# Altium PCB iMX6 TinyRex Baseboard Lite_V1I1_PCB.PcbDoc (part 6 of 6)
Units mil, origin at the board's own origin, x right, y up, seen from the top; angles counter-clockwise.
Board outline 3149.61 x 3543.31 mil, 6 copper layers (L1, L2, L3, L4 (PWR), L5, L6), stack 60.634 mil thick; 385 components, 309 nets, 1566 pads, 914 vias.
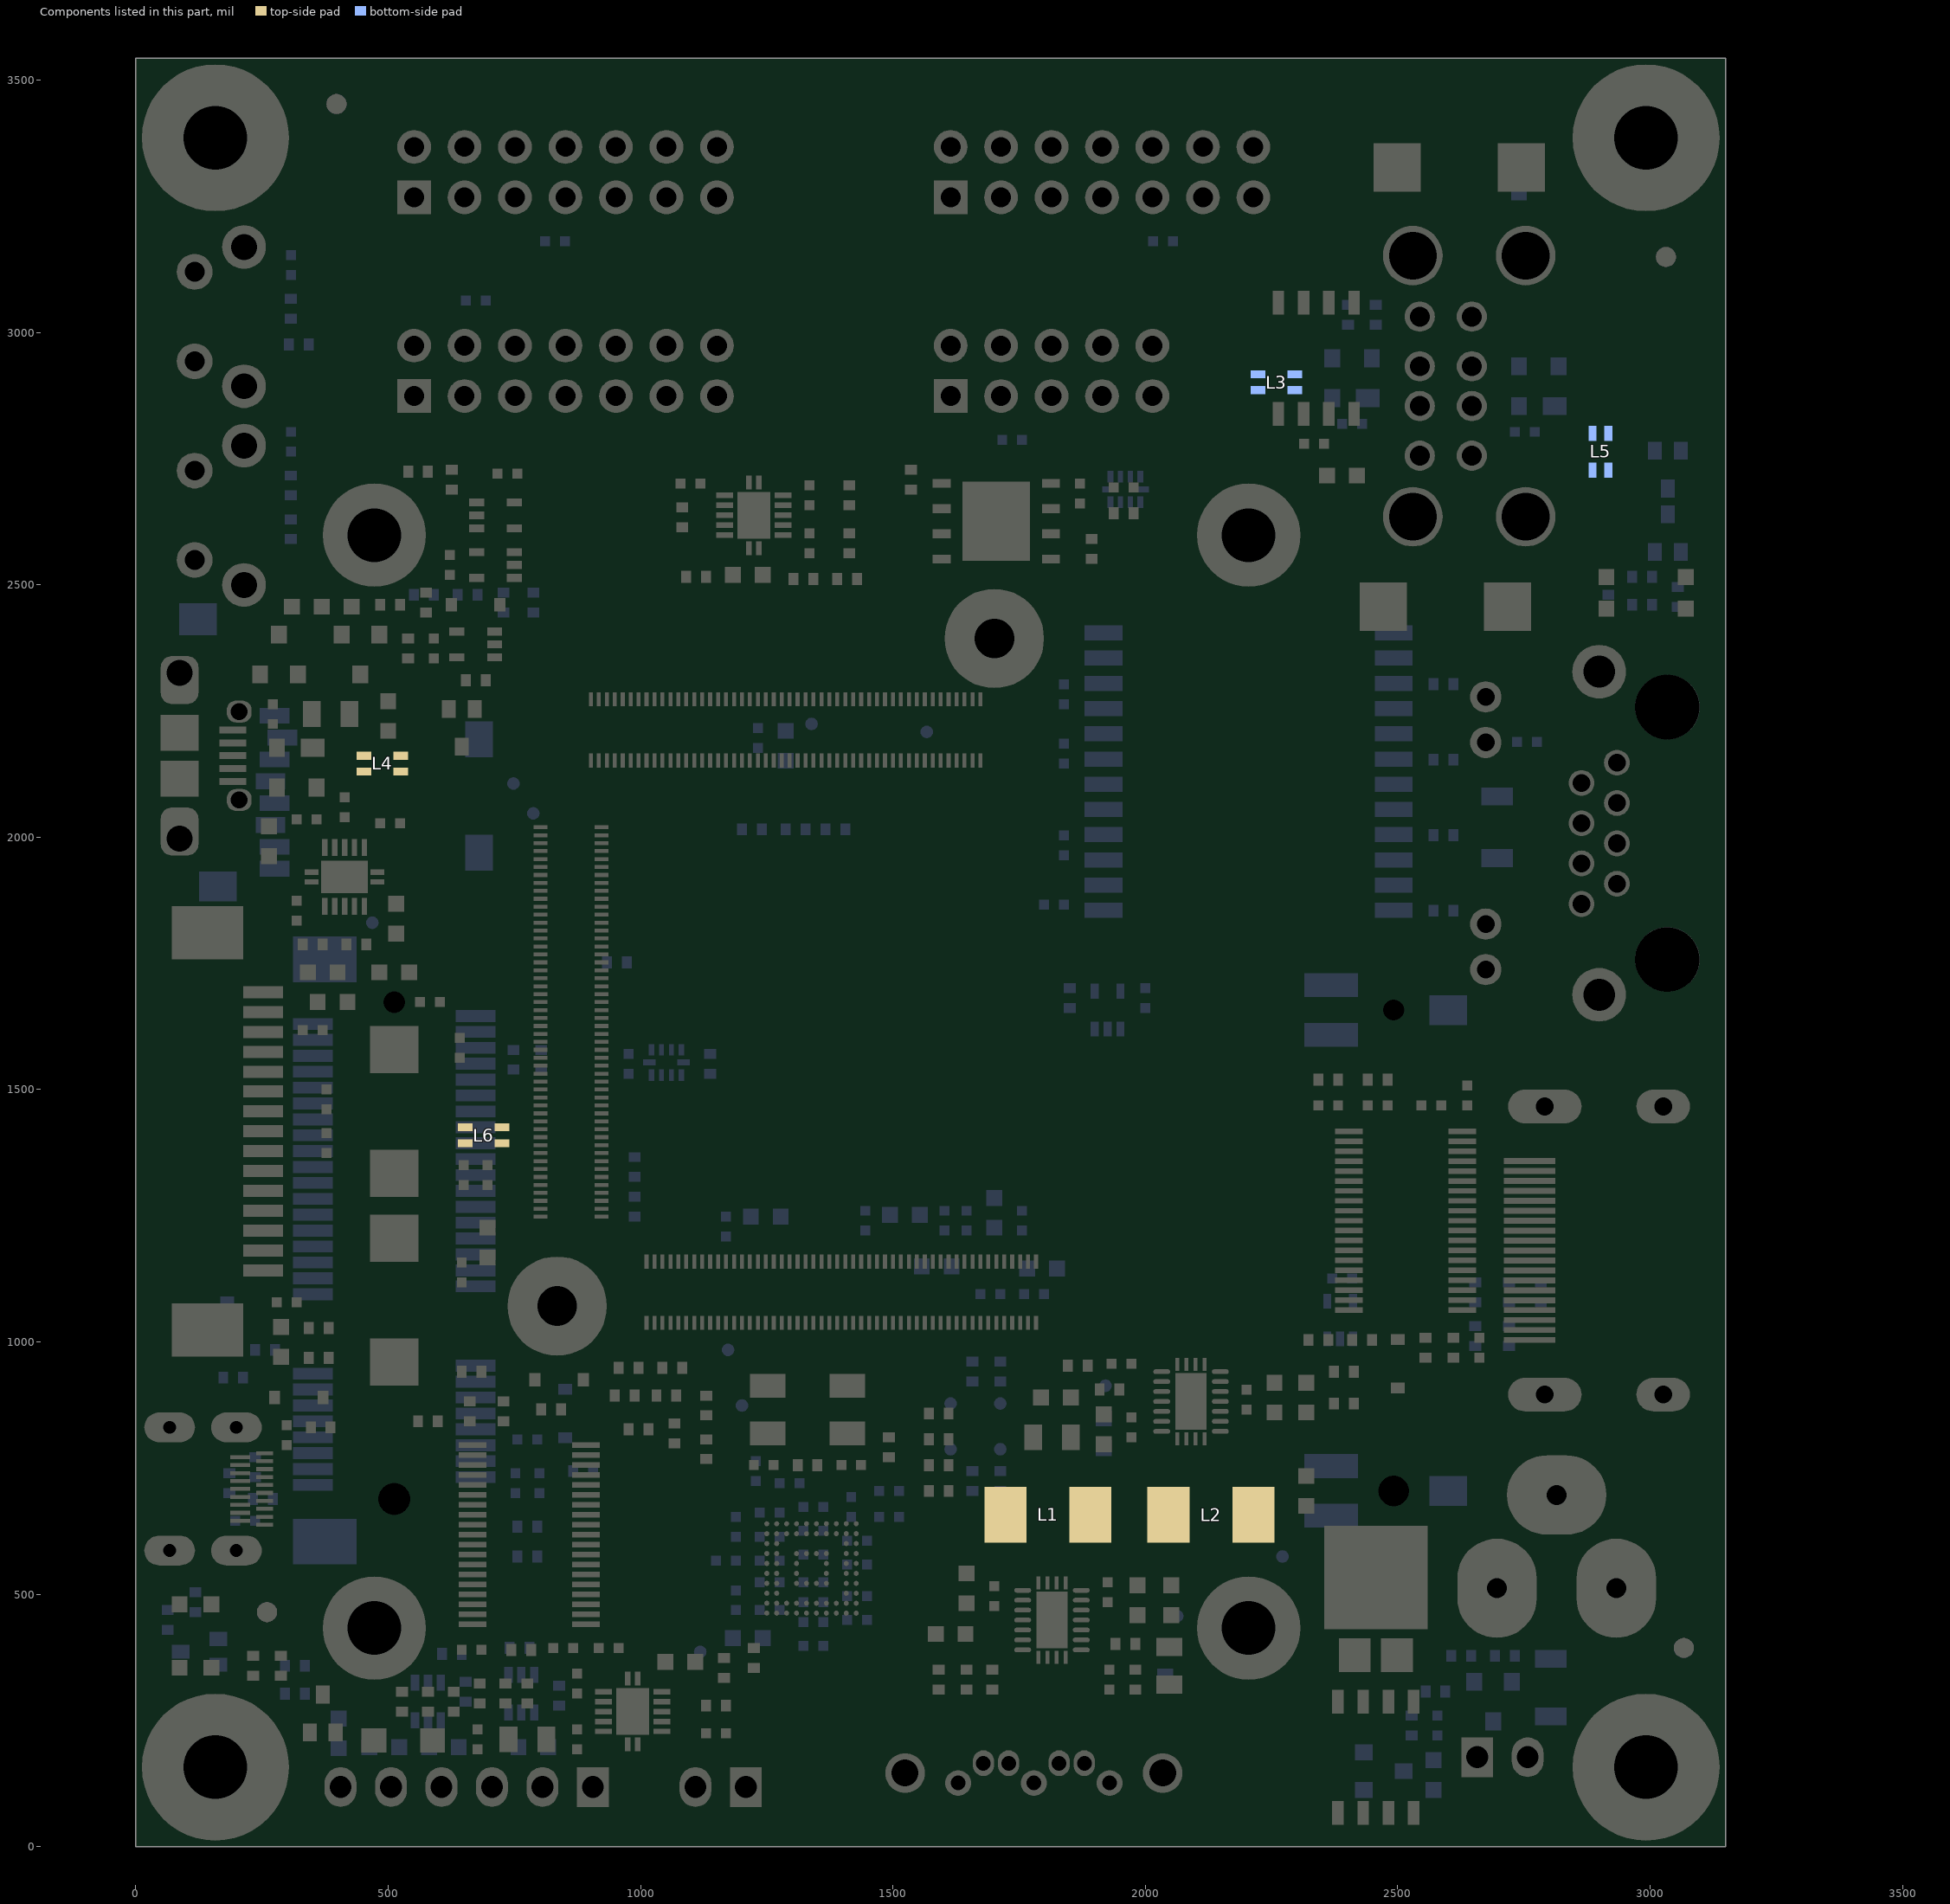
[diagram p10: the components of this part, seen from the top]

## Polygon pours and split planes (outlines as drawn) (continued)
L2_5V on L1 "Power Plane" (solid, pour order 154): 1866.14,484.25 1885.83,484.25 1901.57,500 1905.51,503.94 1905.51,527.56 1905.51,566.93 1917.32,578.74 1933.07,594.49 1933.07,606.3 1933.07,712.6 1850.39,712.6 1850.39,602.36 1850.39,551.18 1866.14,535.43
L1_5V on L1 "Power Plane" (solid, pour order 155): 1763.78,484.25 1763.78,590.55 1763.78,712.6 1681.1,712.6 1681.1,586.61 1712.6,555.12 1720.47,547.24 1720.47,515.75 1720.47,500 1736.22,484.25
GND on L1 "Power Plane" (solid, pour order 156): 1629.92,527.56 1657.48,527.56 1673.23,511.81 1681.1,511.81 1685.04,515.75 1685.04,562.99 1681.1,566.93 1673.23,566.93 1669.29,566.93 1661.42,559.06 1629.92,559.06 1629.92,527.56
GND on L1 "Power Plane" (solid, pour order 157): 1566.93,437.01 1566.93,385.83 1574.8,377.95 1622.05,377.95 1625.98,381.89 1625.98,385.83 1625.98,389.76 1618.11,397.64 1614.17,397.64 1610.24,397.64 1598.43,409.45 1598.43,437.01
GND on L1 "Power Plane" (solid, pour order 158): 2240.16,901.57 2240.16,952.76 2244.09,956.69 2326.77,956.69 2330.71,956.69 2334.65,952.76 2334.65,901.57 2303.15,901.57 2291.34,913.39 2283.46,913.39 2271.65,901.57 2240.16,901.57
+VIN on L1 "Power Plane" (solid, pour order 159): 2149.61,885.83 2149.61,858.27 2173.23,858.27 2212.6,818.9 2326.77,818.9 2334.65,818.9 2334.65,826.77 2334.65,877.95 2232.28,877.95 2192.91,877.95 2185.04,885.83 2173.23,885.83
L2_3V3 on L1 "Power Plane" (solid, pour order 160): 2039.37,846.46 2039.37,795.28 2082.68,751.97 2086.61,748.03 2086.61,700.79 2086.61,602.36 2003.94,602.36 2003.94,736.22 1992.13,748.03 1992.13,826.77 2011.81,846.46
L1_3V3 on L1 "Power Plane" (solid, pour order 161): 2141.73,846.46 2141.73,771.65 2173.23,740.16 2173.23,708.66 2173.23,602.36 2255.91,602.36 2255.91,732.28 2185.04,803.15 2185.04,826.77 2165.35,846.46
+3V3 on L1 "Power Plane" (solid, pour order 162): 22 vertices, not listed, extent 1834.65,783.46 2031.5,917.32
GND on L1 "Power Plane" (solid, pour order 163): 1901.57,811.02 1933.07,811.02 1944.88,799.21 1944.88,755.91 1944.88,751.97 1940.94,748.03 1893.7,748.03 1889.76,751.97 1889.76,787.4 1897.64,795.28 1901.57,799.21 1901.57,811.02
GND on L1 "Power Plane" (solid, pour order 164): 1751.97,858.27 1751.97,905.51 1755.91,909.45 1803.15,909.45 1807.09,905.51 1807.09,870.08 1791.34,854.33 1759.84,854.33 1755.91,854.33 1751.97,858.27
GND on L1 "Power Plane" (solid, pour order 165): 1795.28,838.58 1795.28,771.65 1783.46,759.84 1744.09,759.84 1740.16,763.78 1736.22,767.72 1736.22,783.46 1736.22,787.4 1744.09,795.28 1759.84,811.02 1759.84,838.58 1795.28,838.58
+2V5 on L1 "Power Plane" (solid, pour order 174): 1169.29,2622.05 1169.29,2562.99 1196.85,2535.43 1196.85,2480.31 1196.85,2468.5 1188.98,2460.63 1149.61,2460.63 1122.05,2488.19 1122.05,2535.43 1110.24,2547.24 1110.24,2574.8 1110.24,2590.55 1141.73,2622.05
GND on L1 "Power plane" (solid, pour order 167): 968.5,187.2 1000,187.2 1000,218.7 1015.75,218.7 1015.75,317.13 1000,317.13 1000,348.62 968.5,348.62 968.5,317.13 952.76,317.13 952.76,218.7 968.5,218.7 968.5,187.2
GND on L1 "Power plane" (solid, pour order 168): 332.87,1937.01 332.87,1905.51 364.37,1905.51 364.37,1889.76 462.8,1889.76 462.8,1905.51 494.29,1905.51 494.29,1937.01 462.8,1937.01 462.8,1952.76 364.37,1952.76 364.37,1937.01 332.87,1937.01
GND on L1 "Power plane" (solid, pour order 169): 1240.16,2718.31 1208.66,2718.31 1208.66,2686.81 1192.91,2686.81 1192.91,2588.39 1208.66,2588.39 1208.66,2556.89 1240.16,2556.89 1240.16,2588.39 1255.91,2588.39 1255.91,2686.81 1240.16,2686.81 1240.16,2718.31
+V_INPUT on L1 "Power Plane" (solid, pour order 107): 17 vertices, not listed, extent 2185.04,39.37 2775.59,602.36
+VIN_D on L1 "Power Plane" (solid, pour order 109): 2543.31,263.78 2586.61,307.09 2586.61,413.39 2350.39,413.39 2279.53,342.52 2279.53,263.78
+VIN on L1 "Power Plane" (solid, pour order 111): 22 vertices, not listed, extent 2208.66,433.07 2586.61,877.95
+V_INPUT on L6 "Power Plane" (solid, pour order 123): 27 vertices, not listed, extent 2185.04,78.74 2834.65,586.61
+5V on L6 "Power Plane" (solid, pour order 122): 2724.41,3291.34 2755.91,3291.34 2767.72,3279.53 2767.72,3248.03 2767.72,3240.16 2763.78,3236.22 2716.54,3236.22 2712.6,3240.16 2712.6,3267.72 2712.6,3279.53 2724.41,3291.34
+V_INPUT on L6 "Power Plane" (solid, pour order 121): 2688.98,216.54 2688.98,137.8 2602.36,137.79 2586.61,153.54 2555.12,153.54 2555.12,188.98 2566.93,200.79 2566.93,228.35 2594.49,228.35 2606.3,216.54
+5V_HDMI_IN_CON on L6 "Power Plane" (solid, pour order 114): 20 vertices, not listed, extent 165.35,913.39 275.59,996.06
+3V3 on L6 "Power Plane" (solid, pour order 110): 34 vertices, not listed, extent 2645.67,2157.48 3086.61,2464.57
GND on L6 "Power Plane" (solid, pour order 143): 82.68,1901.57 141.73,1960.63 204.72,1960.63 212.6,1952.76 212.6,1870.08 157.48,1814.96 157.48,1748.03 157.48,1736.22 149.61,1728.35 118.11,1728.35 94.49,1728.35 82.68,1740.16
+VIN on L6 "Power Plane" (solid, pour order 199): 22 vertices, not listed, extent 1181.1,2559.05 1555.12,3425.2
+1V5_MPCIE on L6 "Power Plane" (solid, pour order 195): 44 vertices, not listed, extent 492.13,795.28 787.4,1712.6
+3V3_TVDD on L6 "Power Plane" (solid, pour order 191): 1244.09,622.05 1244.09,555.12 1181.1,555.12 1181.1,622.05 1244.09,622.05
+5V_USB1_VBUS on L6 "Power Plane" (solid, pour order 190): 17 vertices, not listed, extent 2236.22,2984.25 2759.84,3366.14
+5V on L6 "Power Plane" (solid, pour order 186): 1149.61,1216.54 1165.35,1216.54 1177.17,1216.54 1188.98,1228.35 1192.91,1232.28 1192.91,1255.91 1200.79,1263.78 1232.28,1263.78 1232.28,1220.47 1200.79,1188.98 1141.73,1188.98 1137.8,1192.91 1137.8,1204.72
GND on L6 "Power Plane" (solid, pour order 185): 1263.78,1232.28 1263.78,1267.72 1259.84,1271.65 1251.97,1279.53 1251.97,1283.46 1255.91,1287.4 1259.84,1287.4 1275.59,1287.4 1287.4,1275.59 1291.34,1271.65 1291.34,1236.22 1291.34,1232.28 1287.4,1232.28 1263.78,1232.28 1263.78,1263.78
+VIN on L6 "Power Plane" (solid, pour order 184): 30 vertices, not listed, extent 1602.36,1055.12 1783.46,1240.16
+3V3 on L6 "Power Plane" (solid, pour order 183): 27 vertices, not listed, extent 1429.13,1177.17 1625.98,1267.72
GND on L6 "Power Plane" (solid, pour order 182): 1570.87,1133.86 1570.87,1188.98 1566.93,1192.91 1562.99,1196.85 1555.12,1196.85 1515.75,1196.85 1507.87,1188.98 1507.87,1165.35 1539.37,1133.86 1570.87,1133.86
GND on L6 "Power Plane" (solid, pour order 181): 1539.37,1236.22 1570.87,1236.22 1586.61,1251.97 1606.3,1251.97 1614.17,1251.97 1614.17,1283.46 1602.36,1295.28 1547.24,1295.28 1539.37,1287.4
GND on L6 "Power Plane" (solid, pour order 179): 1677.17,1326.77 1724.41,1326.77 1728.35,1322.83 1728.35,1279.53 1720.47,1271.65 1681.1,1271.65 1673.23,1279.53 1673.23,1291.34 1673.23,1322.83 1677.17,1326.77
GND on L6 "Power Plane" (solid, pour order 180): 1866.14,1174.94 1866.14,1122.05 1862.2,1118.11 1818.9,1118.11 1811.02,1125.98 1811.02,1173.23 1826.77,1188.98 1852.11,1188.98
GND on L6 "Power Plane" (solid, pour order 178): 1417.32,503.94 1417.32,440.94 1397.64,440.94 1381.89,456.69 1381.89,500 1389.76,507.87 1417.32,507.87 1417.32,503.94
GND on L6 "Power Plane" (solid, pour order 177): 27 vertices, not listed, extent 1228.35,397.64 1358.27,673.23
+2V5 on L6 "Power Plane" (solid, pour order 176): 1220.47,2208.66 1248.03,2208.66 1259.84,2196.85 1287.4,2196.85 1326.77,2196.85 1350.39,2220.47 1350.39,2232.28 1334.65,2248.03 1228.35,2248.03 1224.41,2244.09 1220.47,2240.16
+3V3_MPCIE on L6 "Power Plane" (solid, pour order 175): 740.16,732.28 807.09,732.28 807.09,751.97 771.65,787.4 759.84,787.4 755.91,787.4 748.03,779.53 740.16,771.65 740.16,732.28
+5V_USB1_VBUS on L6 "Power Plane" (solid, pour order 131): 21 vertices, not listed, extent 2622.05,2728.35 2834.65,2870.08
+5V_USB0_VBUS on L6 "Power Plane" (solid, pour order 132): 19 vertices, not listed, extent 2397.64,2507.87 2547.24,2889.76
GND on L6 "Power Plane" (solid, pour order 133): 2740.16,1976.38 2740.16,1925.2 2732.28,1917.32 2677.17,1917.32 2661.42,1917.32 2653.54,1925.2 2653.54,1976.38
GND on L6 "Power Plane" (solid, pour order 147): 70.87,2488.19 70.87,2413.39 153.54,2330.71 192.91,2330.71 200.79,2330.71 208.66,2338.58 208.66,2413.39 161.42,2460.63 153.54,2468.5 153.54,2480.31 153.54,2488.19 145.67,2496.06 114.17,2496.06 78.74,2496.06
GND on L6 "Power Plane" (solid, pour order 148): 448.82,1696.85 456.69,1704.72 456.69,1795.28 440.94,1811.02 413.39,1838.58 311.02,1838.58 303.15,1838.58 271.65,1807.09 271.65,1740.16 303.15,1708.66 307.09,1708.66 421.26,1708.66 433.07,1696.85 454.72,1696.85
GND on L6 "Power Plane" (solid, pour order 149): 19 vertices, not listed, extent 287.4,492.13 460.63,688.98
+5V on L6 "Power Plane" (solid, pour order 170): 2023.62,381.89 2055.12,381.89 2066.93,393.7 2070.87,397.64 2070.87,433.07 2066.93,437.01 1984.25,437.01 1980.32,437.01 1976.38,433.07 1976.38,425.2 1976.38,421.26 2015.75,381.89 2055.12,381.89
GND on L6 "Power Plane" (solid, pour order 171): 2055.12,350.39 2066.93,350.39 2106.3,311.02 2106.3,291.34 2090.55,275.59 2023.62,275.59 2015.75,283.46 2015.75,342.52 2023.62,350.39 2066.93,350.39
GND on L6 "Power Plane" (solid, pour order 172): 1940.94,803.15 1944.88,799.21 1944.88,751.97 1940.94,748.03 1897.64,748.03 1893.7,748.03 1889.76,751.97 1889.76,791.34 1901.57,803.15
+3V3 on L6 "Power Plane" (solid, pour order 173): 1877.95,893.7 1877.95,814.96 1881.89,811.02 1889.76,811.02 1893.7,814.96 1893.7,818.9 1893.7,822.83 1905.51,834.65 1933.07,834.65 1933.07,921.26 1929.13,925.2 1925.2,925.2 1909.45,925.2 1877.95,893.7 1877.95,885.83
GND on L6 "Power Plane" (solid, pour order 113): 2287.4,732.28 2291.34,728.35 2322.83,728.35 2440.94,728.35 2448.82,736.22 2448.82,791.34 2444.88,791.34 2440.94,795.28 2311.02,795.28 2287.4,771.65 2283.46,767.72 2283.46,740.16 2283.46,736.22 2287.4,732.28
GND on L6 "Power Plane" (solid, pour order 115): 2279.53,696.85 2291.34,708.66 2322.83,708.66 2342.52,688.98 2350.39,681.1 2421.26,681.1 2421.26,629.92 2311.02,629.92 2279.53,661.42
GND on L6 "Power Plane" (solid, pour order 117): 2535.43,732.28 2535.43,677.17 2539.37,673.23 2661.42,673.23 2669.29,681.1 2669.29,732.28 2665.35,736.22 2539.37,736.22
GND on L6 "Power Plane" (solid, pour order 116): 2535.43,1685.04 2535.43,1629.92 2539.37,1625.98 2661.42,1625.98 2669.29,1633.86 2669.29,1685.04 2665.35,1688.98 2539.37,1688.98
GND on L6 "Power Plane" (solid, pour order 119): 2291.34,1590.55 2299.21,1582.68 2440.94,1582.68 2452.76,1594.49 2452.76,1618.11 2437.01,1633.86 2433.07,1633.86 2299.21,1633.86 2291.34,1625.98 2291.34,1590.55
GND on L6 "Power Plane" (solid, pour order 120): 2291.34,1700.79 2314.96,1724.41 2322.83,1732.28 2421.26,1732.28 2433.07,1732.28 2452.76,1712.6 2452.76,1696.85 2452.76,1688.98 2444.88,1681.1 2334.65,1681.1 2314.96,1661.42 2295.28,1661.42 2291.34,1665.35
+3V3 on L3 "Power Plane" (solid, pour order 198): 59.06,236.22 59.06,523.62 244.09,523.62 334.65,433.07 590.55,433.07 712.6,555.12 818.9,555.12 846.46,527.56 846.46,314.96 767.72,236.22
+2V5 on L3 "Power Plane" (solid, pour order 197): 1200.79,2224.41 1240.16,2224.41 1307.09,2224.41 1318.9,2236.22 1318.9,2342.52 1338.58,2362.2 1338.58,2570.87 1318.9,2590.55 1244.09,2590.55 1082.68,2429.13 1082.68,2342.52
+5V on L3 "Power Plane" (solid, pour order 196): 33 vertices, not listed, extent 1968.5,59.06 3090.55,3484.25
+3V3 on L4 (PWR) "Power Plane" (solid, pour order 202): 53 vertices, not listed, extent 59.06,480.31 2677.17,3484.25
+1V8 on L4 (PWR) "Power Plane" (solid, pour order 201): 1106.3,413.39 1181.1,413.39 1220.47,452.76 1279.53,511.81 1437.01,669.29 1496.06,669.29 1496.06,696.85 1464.57,728.35 1161.42,728.35 1161.42,492.13 1141.73,472.44 1082.68,472.44 1082.68,437.01
+VIN on L4 (PWR) "Power Plane" (solid, pour order 200): 62 vertices, not listed, extent 59.05,59.06 3090.55,3484.25
+5V on L4 (PWR) "Power Plane" (solid, pour order 194): 63 vertices, not listed, extent 374.01,267.72 2141.73,2519.69
GND on L2 (split plane): 3145.59,4.01 4.01,4.01 4.01,3539.29 3145.59,3539.29
GND on L5 (split plane): 3145.59,4.01 4.01,4.01 4.01,3539.29 3145.59,3539.29

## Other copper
L6:
  region: 2541.22,3500.79 2541.22,3500.91 2541.22,3501.03 2541.22,3501.16 2541.22,3501.28 2541.22,3501.4 2541.22,3501.52 2541.22,3501.64 2541.22,3501.77 2541.22,3501.89 2541.22,3502.01 2541.22,3502.13 2541.22,3502.25 2541.22,3502.38 2541.22,3502.5 2541.22,3502.62 2541.22,3502.74 2541.22,3502.86 2541.22,3502.99 2541.22,3503.11 2541.22,3503.23 2541.22,3503.35 2541.22,3503.48 2541.22,3503.6 2541.22,3503.72 2541.22,3503.84 2541.22,3503.96 2541.22,3504.09 2541.22,3504.21 2541.22,3504.33 2541.22,3504.45 2541.22,3504.57 2541.22,3504.7 2433.07,3504.7 2433.07,3504.57 2433.07,3504.45 2433.07,3504.33 2433.07,3504.21 2433.07,3504.09 2433.07,3503.96 2433.07,3503.84 2433.07,3503.72 2433.07,3503.6 2433.07,3503.48 2433.07,3503.35 2433.07,3503.23 2433.07,3503.11 2433.07,3502.99 2433.07,3502.86 2433.07,3502.74 2433.07,3502.62 2433.07,3502.5 2433.07,3502.38 2433.07,3502.25 2433.07,3502.13 2433.07,3502.01 2433.07,3501.89 2433.07,3501.77 2433.07,3501.64 2433.07,3501.52 2433.07,3501.4 2433.07,3501.28 2433.07,3501.16 2433.07,3501.03 2433.07,3500.91 2433.07,3500.79 2433.07,3500.67 2541.22,3500.67
  region: 2554.77,3395.2 2554.77,3395.33 2554.77,3395.45 2554.77,3395.57 2554.77,3395.69 2554.77,3395.81 2554.77,3395.94 2554.77,3396.06 2554.77,3396.18 2554.77,3396.3 2554.77,3396.42 2554.77,3396.55 2554.77,3396.67 2554.77,3396.79 2554.77,3396.91 2554.77,3397.03 2554.77,3397.16 2554.77,3397.28 2554.77,3397.4 2554.77,3397.52 2554.77,3397.64 2554.77,3397.77 2554.77,3397.89 2554.77,3398.01 2554.77,3398.13 2554.77,3398.25 2554.77,3398.38 2554.77,3398.5 2554.77,3398.62 2554.77,3398.74 2554.77,3398.87 2554.77,3398.99 2554.77,3399.11 2446.62,3399.11 2446.62,3398.99 2446.62,3398.87 2446.62,3398.74 2446.62,3398.62 2446.62,3398.5 2446.62,3398.38 2446.62,3398.25 2446.62,3398.13 2446.62,3398.01 2446.62,3397.89 2446.62,3397.77 2446.62,3397.64 2446.62,3397.52 2446.62,3397.4 2446.62,3397.28 2446.62,3397.16 2446.62,3397.03 2446.62,3396.91 2446.62,3396.79 2446.62,3396.67 2446.62,3396.55 2446.62,3396.42 2446.62,3396.3 2446.62,3396.18 2446.62,3396.06 2446.62,3395.94 2446.62,3395.81 2446.62,3395.69 2446.62,3395.57 2446.62,3395.45 2446.62,3395.33 2446.62,3395.2 2446.62,3395.08 2554.77,3395.08
  region: 2812 vertices and 0 holes, not listed, extent 2467.25,3412.54 2529.87,3490.17
  region: 1344 vertices and 0 holes, not listed, extent 2677.75,3465.62 2759.66,3504.1
  region: 1381 vertices and 0 holes, not listed, extent 2699.13,3397.75 2762.06,3458.27
  region: 2099 vertices and 0 holes, not listed, extent 2639.01,3396.28 2713.56,3503.97

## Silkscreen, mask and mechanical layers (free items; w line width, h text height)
Top Overlay:
  text "RESET" at 259.84,3122.05 h39.37 r270
  text "USER" at 259.84,2712.6 h39.37 r270
  text "OTG" at 39.37,2480.31 h39.37 r270
  text "USB" at 98.43,2480.31 h39.37 r270
  text "USB TOP" at 2854.33,2381.89 h31.5 r90
  text "USB BOT" at 3011.81,2381.89 h31.5 r90
  text "FEDEVEL" at 2480.31,1803.15 h62.99 r90
  text "(c) 2015" at 2362.2,1787.4 h62.99 r90
  text "& VOIPAC" at 2598.43,1775.59 h62.99 r90
  text "POSITIVE IN" at 2732.28,803.15 h39.37
  text "IN:" at 2519.69,767.72 h39.37 r90
  text "CENTER" at 2909.45,740.16 h39.37
  text "+3.2 to" at 2578.74,649.61 h39.37 r90
  text "5.3V DC" at 2637.8,649.61 h39.37 r90
  text "PWR" at 11.81,523.62 h31.5 r270
  text "USER" at 11.81,405.51 h31.5 r270
  text "G" at 393.7,11.81 h39.37
  text "Y" at 492.13,11.81 h39.37
  text "O" at 594.49,11.81 h39.37
  text "R" at 696.85,11.81 h39.37
  text "Br" at 783.46,11.81 h39.37
  text "Bl" at 885.83,11.81 h39.37
  text "BOOT MODE" at 988.19,11.81 h39.37
Bottom Overlay:
  lines w10: 919.52,2283.49 919.52,2381.92 ; 1037.63,2283.49 1037.63,2381.92 ; 1155.74,2283.49 1155.74,2381.92 ; 1273.85,2283.49 1273.85,2381.92 ; 1391.96,2283.49 1391.96,2381.92 ; 1830.71,323.26 1948.82,323.26 ; 1830.71,441.37 1948.82,441.37 ; 801.41,2283.49 1510.07,2283.49 1510.07,2381.92 801.41,2381.92 801.41,2283.49 ; 1830.71,205.15 1830.71,559.48 1948.82,559.48 1948.82,205.15 1830.71,205.15
  text "PERIPHERALS" at 657.48,3472.44 h39.37 r180
  text "SYSTEM" at 1803.15,3472.44 h39.37 r180
  text "UARTS" at 759.84,3078.74 h39.37 r180
  text "GPIO & PWM" at 1625.98,3078.74 h39.37 r180
  text "USB" at 3110.24,2952.76 h39.37 r90
  text "(c) fedevel.com & voipac.com" at 622.05,2704.72 h46.46 r180
  text "iMX6 TinyRex BB Lite V1I1" at 606.3,2594.49 h62.99 r180
  text "A" at 840.78,2362.23 h60 r180
  text "B" at 958.89,2362.23 h60 r180
  text "C" at 1077,2362.23 h60 r180
  text "D" at 1195.11,2362.23 h60 r180
  text "E" at 1313.22,2362.23 h60 r180
  text "F" at 1431.33,2362.23 h60 r180
  text "MODBOX" at 807.09,2244.09 h51.18 r180
  text "ETHERNET" at 3090.55,2165.35 h39.37 r90
  text "+2V5" at 1374.02,2094.49 h39.37 r270
  text "+1V2" at 1551.18,2019.69 h39.37 r270
  text "FEDEVEL Academy" at 921.26,1944.88 h50 r180
  text "Designed by" at 1031.5,1850.39 h50 r180
  text "+1V5" at 519.69,1834.65 h39.37 r180
  text "HDMI OUT" at 3090.55,1338.58 h39.37 r90
  text "CAMERA IN" at 39.37,1240.16 h39.37 r270
  text "+3V3" at 1901.57,960.63 h39.37 r270
  text "+3V0 ALW" at 1078.74,897.64 h39.37 r270
  text "GND" at 1263.78,818.9 h39.37 r270
  text "INPUT" at 3043.31,787.4 h39.37 r90
  text "POWER" at 3110.24,787.4 h39.37 r90
  text "IN" at 39.37,681.1 h39.37 r270
  text "BOARD" at 2007.87,669.29 h51.18
  text "HDMI" at 106.3,641.73 h39.37 r270
  text "+VIN" at 2212.6,598.43 h39.37 r270
  text "VARIANT:" at 2007.87,590.55 h51.18
  text "to" at 1614.17,511.81 h39.37
  text "+3.2" at 1791.34,511.81 h39.37
  text "+5V" at 2043.31,488.19 h39.37 r270
  text "+5.3V" at 1791.34,452.76 h39.37
  text "+1V8" at 1047.24,425.2 h39.37 r270
  text "+5V" at 1791.34,358.27 h39.37
  text "CUSTOM" at 1791.34,236.22 h39.37
  text "TTL-232R-3V3 FTDI" at 976.38,27.56 h39.37
  text "SATA" at 1866.14,27.56 h39.37
  text "POWER HEADER" at 2846.46,27.56 h39.37
Bottom Solder:
  drawing of 6 lines, arcs and shapes, not listed
Mechanical Drawing All:
  circle w23.62: c511.81,1673.23 r9.84
  circle w35.43: c511.81,688.98 r14.76
  circle w39.37: c2992.13,3385.83 r62.99
  circle w23.62: c834.65,1070.87 r39.37
  circle w39.37: c157.48,3385.83 r62.99
  circle w39.37: c157.48,157.48 r62.99
  circle w39.37: c2992.13,157.48 r62.99
  circle w39.37: c472.44,2598.43 r53.15
  circle w39.37: c472.44,433.07 r53.15
  circle w39.37: c2204.72,2598.43 r53.15
  circle w23.62: c1700.79,2393.7 r39.37
  circle w39.37: c2204.72,433.07 r53.15
  circle w31.5: c2492.13,704.72 r14.76
  circle w31.5: c2492.13,704.72 r14.76
  circle w21.65: c2492.13,1657.48 r9.84
  lines w7.87: -106.3,2161.42 76.77,2161.42 ; -84.49,2112.2 98.58,2112.2 ; 6.1,2637.8 108.46,2637.8 ; 6.1,3031.5 108.46,3031.5 ; 37.4,708.66 220.47,708.66 ; 68.9,1417.32 251.97,1417.32 ; 2969.68,2007.87 3152.76,2007.87 ; 2986.22,2893.7 3153.54,2893.7 ; 2988.19,1181.1 3149.61,1181.1 ; 3068.9,511.81 3149.61,511.81
  lines w39.37: 0,0 0,3543.31 3149.61,3543.31 3149.61,0 0,0
  text "Mechanical Drawing - All" at 0,4429.13 h137.8
  text "iMX6 TinyRex Baseboard Lite" at -492.13,4035.43 h137.8
  text ".VersionRevision" at 3248.03,4035.43 h137.8
  text "(Scale 1:1)" at 1082.68,-1870.08 h60
Manufacturing Notes:
  circle w39.37: c9842.52,5511.81 r9.84
  circle w39.37: c9842.52,3937.01 r9.84
  circle w39.37: c6200.79,3937.01 r9.84
  circle w39.37: c6200.79,5511.81 r9.84
  lines w7.87: 5364.17,4724.41 5413.39,4724.41 ; 5905.51,4724.41 5964.57,4724.41 ; 6102.36,3592.52 9940.94,3592.52 ; 6131.89,3956.69 6181.1,3956.69 6181.1,4005.91 ; 6131.89,5492.13 6181.1,5492.13 6181.1,5442.91 ; 6200.79,3937.01 5413.39,4724.41 ; 6200.79,5511.81 5413.39,4724.41 ; 6259.84,3553.15 6299.21,3592.52 6259.84,3631.89 ; 6299.21,3543.31 6299.21,3838.58 ; 6348.43,5413.39 6348.43,5364.17 ; 6397.64,3543.31 6397.64,3838.58 ; 6397.64,5364.17 6348.43,5364.17 ; 6437.01,3553.15 6397.64,3592.52 6437.01,3631.89 ; 6781.5,3858.27 6830.71,3858.27 6830.71,3907.48 ; 6781.5,5590.55 6830.71,5590.55 6830.71,5541.34 ; 6850.39,3838.58 5964.57,4724.41 ; 6850.39,5610.24 5964.57,4724.41 ; 7677.17,3346.46 8169.29,3346.46 ; 7933.07,3307.09 7972.44,3346.46 7933.07,3385.83 ; 7933.07,3553.15 7972.44,3592.52 7933.07,3631.89 ; 7972.44,3297.24 7972.44,3838.58 ; 7982.28,5551.18 8021.65,5511.81 ; 8021.65,6102.36 8021.65,5511.81 ; 8061.02,5551.18 8021.65,5511.81 ; 8070.87,3297.24 8070.87,3838.58 ; 8110.24,3307.09 8070.87,3346.46 8110.24,3385.83 ; 8110.24,3553.15 8070.87,3592.52 8110.24,3631.89 ; 9192.91,3838.58 10078.74,4724.41 ; 9192.91,5610.24 10078.74,4724.41 ; 9212.6,3907.48 9212.6,3858.27 9261.81,3858.27 ; 9212.6,5541.34 9212.6,5590.55 9261.81,5590.55 ; 9606.3,3553.15 9645.67,3592.52 9606.3,3631.89 ; 9645.67,3543.31 9645.67,3838.58 ; 9645.67,5364.17 9694.88,5364.17 ; 9694.88,5413.39 9694.88,5364.17 ; 9744.09,3543.31 9744.09,3789.37 ; 9744.09,3838.58 11614.17,3838.58 ; 9744.09,5610.24 11614.17,5610.24 ; 9783.46,3553.15 9744.09,3592.52 9783.46,3631.89 ; 9842.52,3937.01 10629.92,4724.41 ; 9842.52,5511.81 10629.92,4724.41 ; 9862.2,4005.91 9862.2,3956.69 9911.42,3956.69 ; 9862.2,5442.91 9862.2,5492.13 9911.42,5492.13 ; 9940.94,3740.16 11811.02,3740.16 ; 9940.94,5708.66 11811.02,5708.66 ; 10137.8,4724.41 10078.74,4724.41 ; 10679.13,4724.41 10629.92,4724.41 ; 11476.38,3877.95 11515.75,3838.58 ; 11476.38,5570.87 11515.75,5610.24 ; 11555.12,3877.95 11515.75,3838.58 ; 11555.12,5570.87 11515.75,5610.24 ; 11722.44,3779.53 11761.81,3740.16 ; 11722.44,5669.29 11761.81,5708.66 ; 11801.18,3779.53 11761.81,3740.16 ; 11801.18,5669.29 11761.81,5708.66 ; 6348.43,5364.17 6988.19,6003.94 7972.44,6003.94 8021.65,6053.15 8070.87,6003.94 9055.12,6003.94 ; 9055.12,6003.94 9694.88,5364.17 ; 9055.12,6003.94 9055.12,6003.94 ; 11515.75,3838.58 11515.75,5610.24 ; 11761.81,3740.16 11761.81,5708.66
  lines w10: -19.68,-2952.76 3622.05,-2952.76 ; -19.68,-2949.8 -19.68,-2556.1 ; -19.68,-2165.35 3622.05,-2165.35 ; 1555.12,-2559.06 1555.12,-2165.35 ; 2933.07,-2165.35 2933.07,-1870.08 ; 3622.05,-2949.8 3622.05,-2556.1 ; -19.68,-2559.06 3622.05,-2559.06 3622.05,-1870.08 -19.68,-1870.08 -19.68,-2559.06
  lines w15.75: 5847.4,2409.45 11731.34,2409.45 ; 5847.4,2683.46 11731.34,2683.46 ; 11692.91,3051.18 5875.98,3051.18 ccw(c5875.98,2962.6) 5787.4,2962.6 5787.4,-108.27 ccw(c5875.98,-108.27) 5875.98,-196.85 11702.76,-196.85 ccw(c11702.76,-108.27) 11791.34,-108.27 11791.34,2962.6 ccw(c11702.76,2962.6) 11702.76,3051.18
  lines w19.68: 6114.17,3838.58 6299.21,3838.58 ; 6114.17,5610.24 6299.21,5610.24 ; 6397.64,5598.43 6397.64,3838.58 cw(c6348.43,3838.58) 6299.21,3838.58 ; 6397.64,5610.24 ccw(c6348.43,5610.24) 6299.21,5610.24 ; 6409.45,3838.58 7960.63,3838.58 ; 6409.45,5610.24 7960.63,5610.24 7972.44,5598.43 7972.44,3838.58 ccw(c8021.65,3838.58) 8070.87,3838.58 8070.87,5610.24 ccw(c8021.65,5610.24) 7972.44,5610.24 ; 8082.68,3838.58 9633.86,3838.58 ; 8082.68,5610.24 9633.86,5610.24 ; 9929.13,3838.58 9744.09,3838.58 ; 9929.13,5610.24 9744.09,5610.24 ; 6299.21,3838.58 6299.21,5610.24 ; 9744.09,3838.58 cw(c9694.88,3838.58) 9645.67,3838.58 9645.67,5610.24 cw(c9694.88,5610.24) 9744.09,5610.24 ; 9744.09,3838.58 9744.09,5610.24 ; 6102.36,3740.16 9940.94,3740.16 9940.94,5708.66 6102.36,5708.66 6102.36,3740.16
  text "Board info" at 5787.4,9842.52 h60
  text "Minimum Track: 100um" at 5787.4,9744.09 h60
  text "Minimum Gap: 75um" at 5787.4,9645.67 h60
  text "Minimum Through Hole VIA: 0.45mm (pad) / 0.2mm (drill). Drilling: L1-L6" at 5787.4,9547.24 h60
  text "1. REMOVE ALL NON-FUNCTIONAL INNER LAYER PADS." at 5787.4,9350.39 h60
  text "2. THIS BOARD CONTAINS IMPEDANCE CONTROLLED TRACKS, TRACK AND GAP SIZES ARE AS FOLLOWS:" at 5787.4,9153.54 h60
  text "TYPE;" at 5984.25,8956.69 h60
  text "Impedance;" at 6476.38,8956.69 h60
  text "Layer (Reference);" at 7362.2,8956.69 h60
  text "Width (mil);" at 8740.16,8956.69 h60
  text "Gap (mil);" at 9527.56,8956.69 h60
  text "DIFF;" at 5984.25,8759.84 h60
  text "90ohm;" at 6476.38,8759.84 h60
  text "L1(L2), L6(L5);" at 7362.2,8759.84 h60
  text "6" at 8740.16,8759.84 h60
  text "6.99" at 9527.56,8759.84 h60
  text "DIFF;" at 5984.25,8661.42 h60
  text "90ohm;" at 6476.38,8661.42 h60
  text "L3(L2,L4)" at 7362.2,8661.42 h60
  text "6.7" at 8740.16,8661.42 h60
  text "7.6" at 9527.56,8661.42 h60
  text "DIFF;" at 5984.25,8464.57 h60
  text "100ohm;" at 6476.38,8464.57 h60
  text "L1(L2), L6(L5);" at 7362.2,8464.57 h60
  text "5.4" at 8740.16,8464.57 h60
  text "10.51" at 9527.56,8464.57 h60
  text "DIFF;" at 5984.25,8366.14 h60
  text "100ohm;" at 6476.38,8366.14 h60
  text "L3(L2,L4)" at 7362.2,8366.14 h60
  text "6" at 8740.16,8366.14 h60
  text "11.09" at 9527.56,8366.14 h60
  text "SE;" at 5984.25,8169.29 h60
  text "55ohm;" at 6476.38,8169.29 h60
  text "L1(L2), L6(L5);" at 7362.2,8169.29 h60
  text "5.4" at 8740.16,8169.29 h60
  text "SE;" at 5984.25,8070.87 h60
  text "55ohm;" at 6476.38,8070.87 h60
  text "L3(L2,L4)" at 7362.2,8070.87 h60
  text "5.9" at 8740.16,8070.87 h60
  text "3. FINISHED PANEL THICKNESS IS NOT CRITICAL: TO BE APPROXIMATELY 1.6mm" at 5787.4,7874.02 h60
  text "4. BOARD FINISH: IMMERSION Au/ELECTROLESS Ni; 0.05-0.12 um GOLD; 3-6um NICKEL" at 5787.4,7677.17 h60
  text "5. SOLDER RESIST: APPLY TO BOTH SIDES COLOUR - GLOSSY BLACK" at 5787.4,7480.31 h60
  text "6. COMPONENT IDENT: COLOUR TO BE WHITE" at 5787.4,7283.46 h60
  text "7. PANELIZE THE BOARD (2PCS PER PANEL). PLACE FIDUCIALS ON THE PANEL STRIPS AS FOLLOWS:" at 5787.4,7086.61 h60
  text "- FIDUCIAL DIAMTER 1-1.5MM, SOLDER MASK OPENING AT LEAST 1MM GREATER THAN FIDUCIAL" at 5984.25,6988.19 h60
  text "- MINIMUM 4MM DISTANCE FROM THE PANEL EDGE" at 5984.25,6889.76 h60
  text "- 3 FIDUCIALS SHOULD LIE ON TWO LINES THAT INTERSECT AT A RIGHT ANGLE" at 5984.25,6791.34 h60
  text "- PLACE ONE FIDUCIAL INTO EACH PANEL CORNER (FOUR ON THE TOP AND FOUR ON THE BOTTOM LAYER)" at 5984.25,6692.91 h60
  text "PANEL DRAWING (NOT IN SCALE):" at 6000,6500 h60
  text "- NOT SPECIFIED DIMENSIONS ARE NOT CRITICAL. CAN BE CHOSEN BY PCB MANUFACTURER" at 6000,6401.57 h60
  text "CUT-OUT" at 7820.87,6155.51 h60
  text "Files" at 78.74,5610.24 h60
  text "*.GTO - Top Overlay" at 78.74,5511.81 h60
  text "*.GTP - Top Paste" at 78.74,5413.39 h60
  text "*.GTS - Top Solder" at 78.74,5314.96 h60
  text "*.GTL - L1 (Positive)" at 78.74,5216.54 h60
  text "*.GP1 - L2 (Negative)" at 78.74,5118.11 h60
  text "*.G1 - L3 (Positive)" at 78.74,5019.69 h60
  text "*.G2 - L4 (Positive)" at 78.74,4921.26 h60
  text "*.GP2 - L5 (Negative)" at 78.74,4822.83 h60
  text "*.GBL - L6 (Positive)" at 78.74,4724.41 h60
  text "FIDUCIALS" at 4822.83,4675.2 h60
  text "V-CUT" at 5561.02,4675.2 h60
  text "V-CUT" at 10187.01,4675.2 h60
  text "FIDUCIALS" at 10728.35,4675.2 h60
  text "*.GBS - Bottom Solder" at 78.74,4625.98 h60
  text "PCB" at 6889.76,4625.98 h200
  text "PCB" at 8562.99,4625.98 h200
  text "90mm" at 11466.54,4625.98 h60 r90
  text "100mm" at 11712.6,4576.77 h60 r90
  text "*.GBP - Bottom Paste" at 78.74,4527.56 h60
  text "*.GBO - Bottom Overlay" at 78.74,4429.13 h60
  text "*.GM3 - Manufacturing Notes" at 78.74,4330.71 h60
  text "*.GM6 - Mechanical Drawing" at 78.74,4232.28 h60
  text "*.GM28 - Board Outline" at 78.74,4133.86 h60
  text "5mm" at 6053.15,3641.73 h60
  text "80mm" at 7086.61,3641.73 h60
  text "80mm" at 8759.84,3641.73 h60
  text "5mm" at 9842.52,3641.73 h60
  text "5mm" at 7677.17,3395.67 h60
  text "Layer Stack Up Detail for: iMX6 TinyRex Baseboard Lite V1I1_PCB.PcbDoc" at 5847.4,2824.8 h62.99
  text "Layer" at 5847.4,2581.1 h62.99
  text "Gerber" at 7623.19,2581.1 h62.99
  text "Copper" at 8536.13,2581.1 h62.99
  text "Dielectric" at 9453.5,2581.1 h62.99
  text "Dielectric" at 10536.17,2581.1 h62.99
  text "Name" at 5847.4,2455.12 h62.99
  text "Document" at 7623.19,2455.12 h62.99
  text "Thickness" at 8536.13,2455.12 h62.99
  text "Height" at 9453.5,2455.12 h62.99
  text "Constant (approx.)" at 10536.17,2455.12 h62.99
  text "Top Solder Mask" at 5847.4,2251.67 h88.58
  text "(.GTS)" at 7623.19,2251.67 h88.58
  text "L1" at 5847.4,1951.87 h88.58
  text "(.GTL)" at 7623.19,1951.87 h88.58
  text "1.25mil" at 8536.13,1951.87 h88.58
  text "4.64mil" at 9453.5,1801.97 h88.58
  text "4.3" at 10536.17,1801.97 h88.58
  text "L2" at 5847.4,1652.07 h88.58
  text "(.GP1)" at 7623.19,1652.07 h88.58
  text "0.69mil" at 8536.13,1652.07 h88.58
  text "5.5mil" at 9453.5,1502.17 h88.58
  text "3.95" at 10536.17,1502.17 h88.58
  text "L3" at 5847.4,1352.26 h88.58
  text "(.G1)" at 7623.19,1352.26 h88.58
  text "0.69mil" at 8536.13,1352.26 h88.58
  text "35.11mil" at 9453.5,1202.36 h88.58
  text "4.45" at 10536.17,1202.36 h88.58
  text "L4 (PWR)" at 5847.4,1052.46 h88.58
  text "(.G2)" at 7623.19,1052.46 h88.58
  text "0.69mil" at 8536.13,1052.46 h88.58
  text "5.5mil" at 9453.5,902.56 h88.58
  text "3.95" at 10536.17,902.56 h88.58
  text "L5" at 5847.4,752.66 h88.58
  text "(.GP2)" at 7623.19,752.66 h88.58
  text "0.69mil" at 8536.13,752.66 h88.58
  text "4.64mil" at 9453.5,602.76 h88.58
  text "4.3" at 10536.17,602.76 h88.58
  text "L6" at 5847.4,452.86 h88.58
  text "(.GBL)" at 7623.19,452.86 h88.58
  text "1.25mil" at 8536.13,452.86 h88.58
  text "Bottom Solder Mask" at 5847.4,153.05 h88.58
  text "(.GBS)" at 7623.19,153.05 h88.58
  text "iMX6 TinyRex BB Lite" at 98.43,-2066.93 h118.11
  text ".VersionRevision" at 3031.5,-2066.93 h118.11
  text "Copyright 2015" at 177.17,-2362.2 h60
  text "Designed by FEDEVEL" at 1751.97,-2362.2 h60
  text "FEDEVEL & VOIPAC" at 177.17,-2460.63 h60
  text "www.fedevel.com" at 1751.97,-2460.63 h60
  text "Contact:" at 177.17,-2755.91 h60
  text "robert.feranec@fedevel.com" at 767.72,-2755.91 h60
Mechanical Drawing:
  circle w39.37: c2204.72,433.07 r53.15
  circle w23.62: c1700.79,2393.7 r39.37
  circle w39.37: c2204.72,2598.43 r53.15
  circle w39.37: c472.44,433.07 r53.15
  circle w39.37: c472.44,2598.43 r53.15
  circle w39.37: c2992.13,157.48 r62.99
  circle w39.37: c157.48,157.48 r62.99
  circle w39.37: c157.48,3385.83 r62.99
  circle w23.62: c834.65,1070.87 r39.37
  circle w39.37: c2992.13,3385.83 r62.99
  lines w39.37: 0,0 3149.61,0 3149.61,3543.31 0,3543.31 0,0 ; 354.33,314.96 2322.83,314.96 2322.83,2716.54 354.33,2716.54 354.33,314.96 ; 748.03,984.25 748.03,2480.31 2244.09,2480.31 2244.09,984.25 748.03,984.25
  text "Mechanical Drawing" at 393.7,5216.54 h137.8
  text "of iMX6 TinyRex Baseboard Lite" at -688.98,4822.83 h137.8
  text ".VersionRevision" at 3444.88,4822.83 h137.8
  text "Suggested heatsink dimensions" at 492.13,2763.78 h59.06
  text "Module dimensions" at 984.25,2519.69 h59.06
  text "(Scale 1:1)" at 1082.68,-1082.68 h60
Board Outline:
  the board outline again, w7.87
ASM Top:
  text "Assembly TOP of iMX6 TinyRex Baseboard Lite" at 177.17,3799.21 h60
  text ".VersionRevision" at 2748.03,3799.21 h60
  text ".VariantName" at 1220.47,3641.73 h60
  text "For manual soldering" at -551.18,2342.52 h27.56
  text "use top side only" at -551.18,2283.46 h27.56
  text "IMPORTANT" at 1492.13,1751.97 h59.06
  text "Connectors must be" at 1488.19,1700.79 h27.56
  text "soldered exactly" at 1488.19,1649.61 h27.56
  text "into the center" at 1488.19,1598.43 h27.56
  text "." at -590.55,1574.8 h0.01
  text "." at 3740.16,1574.8 h0.01
  text "of the footprint" at 1488.19,1547.24 h27.56
ASM Bottom:
  text ".VersionRevision" at 255.91,3799.21 h60
  text "Assembly BOTTOM of iMX6 TinyRex Baseboard Lite" at 3000,3799.21 h60
  text ".VariantName" at 1850.39,3641.73 h60

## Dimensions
2657.48,177.17 to 3149.61,0 on Mechanical Drawing All
74.8,2165.35 to -98.43,2165.35 on Mechanical 16
0,0 to 2657.48,177.17 on Mechanical Drawing All
0,0 to 511.81,1673.23 on Mechanical Drawing All
0,3543.31 to 1614.17,3267.72 on Mechanical Drawing All
0,3543.31 to 551.18,3267.72 on Mechanical Drawing All
354.33,314.96 to 354.33,2716.54 on Mechanical Drawing
354.33,314.96 to 472.44,433.07 on Mechanical Drawing
748.03,984.25 to 748.03,2480.31 on Mechanical Drawing
748.03,984.25 to 834.65,1070.87 on Mechanical Drawing
834.65,1070.87 to 1700.79,2393.7 on Mechanical Drawing
834.65,1070.87 to 1700.79,2393.7 on Mechanical Drawing
472.44,433.07 to 2204.72,2598.43 on Mechanical Drawing
0,0 to 157.48,157.48 on Mechanical Drawing
0,0 to 472.44,2598.43 on Mechanical Drawing
0,0 to 834.65,1070.87 on Mechanical Drawing
157.48,157.48 to 2992.13,157.48 on Mechanical Drawing
0,0 to 3149.61,0 on Mechanical Drawing
0,0 to 157.48,157.48 on Mechanical Drawing
0,0 to 472.44,433.07 on Mechanical Drawing
0,0 to 834.65,1070.87 on Mechanical Drawing
472.44,433.07 to 472.44,2598.43 on Mechanical Drawing
157.48,157.48 to 157.48,3385.83 on Mechanical Drawing
0,0 to 0,3543.31 on Mechanical Drawing
2204.72,433.07 to 2086.61,511.81 on Mechanical Drawing
1700.79,2393.7 to 1822.83,2322.83 on Mechanical Drawing
834.65,1070.87 to 984.25,1181.1 on Mechanical Drawing
2204.72,2598.43 to 2420.75,2814.45 on Mechanical Drawing
472.44,433.07 to 590.55,551.18 on Mechanical Drawing
472.44,2598.43 to 294.16,2776.7 on Mechanical Drawing
2992.13,157.48 to 2834.65,275.59 on Mechanical Drawing
157.48,157.48 to -54.99,-54.99 on Mechanical Drawing
157.48,3385.83 to 314.96,3267.72 on Mechanical Drawing
2992.13,3385.83 to 2834.65,3307.09 on Mechanical Drawing
354.33,2716.54 to 2322.83,2716.54 on Mechanical Drawing
748.03,984.25 to 2244.09,984.25 on Mechanical Drawing
472.44,433.07 to 354.33,314.96 on Mechanical Drawing
834.65,1070.87 to 748.03,984.25 on Mechanical Drawing
0,0 to 0,3543.31 on Mechanical Drawing All
0,0 to 157.48,3385.83 on Mechanical Drawing All
0,0 to 6.1,3031.5 on Mechanical Drawing All
0,0 to 6.1,2637.8 on Mechanical Drawing All
37.4,2112.2 to 0,0 on Mechanical Drawing All
0,0 to 68.9,1417.32 on Mechanical Drawing All
0,0 to 76.77,2161.42 on Mechanical Drawing All
0,0 to 1614.17,3267.72 on Mechanical Drawing All
0,0 to 1614.17,2874.02 on Mechanical Drawing All
0,0 to 2986.22,2893.7 on Mechanical Drawing All
0,0 to 472.44,2598.43 on Mechanical Drawing All
0,0 to 1700.79,2393.7 on Mechanical Drawing All
0,0 to 2969.68,2007.87 on Mechanical Drawing All
0,0 to 2988.19,1181.1 on Mechanical Drawing All
0,0 to 2492.13,704.72 on Mechanical Drawing All
0,0 to 834.65,1070.87 on Mechanical Drawing All
0,0 to 37.4,708.66 on Mechanical Drawing All
0,0 to 3068.9,511.81 on Mechanical Drawing All
0,0 to 511.81,688.98 on Mechanical Drawing All
0,0 to 472.44,433.07 on Mechanical Drawing All
0,0 to 157.48,157.48 on Mechanical Drawing All
0,0 to 1929.13,125.98 on Mechanical Drawing All
0,0 to 1208.66,118.11 on Mechanical Drawing All
0,0 to 3149.61,0 on Mechanical Drawing All
0,0 to 2992.13,3385.83 on Mechanical Drawing All
0,0 to 2492.13,1657.48 on Mechanical Drawing All
0,0 to 2204.72,2598.43 on Mechanical Drawing All
0,0 to 511.81,1673.23 on Mechanical Drawing All
0,0 to 1700.79,2393.7 on Mechanical Drawing All
0,0 to 1929.13,125.98 on Mechanical Drawing All
0,0 to 1208.66,118.11 on Mechanical Drawing All
0,0 to 905.51,118.11 on Mechanical Drawing All
0,0 to 834.65,1070.87 on Mechanical Drawing All
0,0 to 472.44,2598.43 on Mechanical Drawing All
0,0 to 157.48,3385.83 on Mechanical Drawing All
1358.27,2141.73 to 1417.32,1673.23 on Mechanical 16
1358.27,1169.29 to 1417.32,1673.23 on Mechanical 16
933.07,1673.23 to 1448.82,1673.23 on Mechanical 16
2992.13,3385.83 to 2834.65,3307.09 on Mechanical Drawing All
157.48,3385.83 to 315.81,3227.5 on Mechanical Drawing All
157.48,157.48 to -54.99,-54.99 on Mechanical Drawing All
2992.13,157.48 to 2834.65,275.59 on Mechanical Drawing All
472.44,2598.43 to 294.16,2776.7 on Mechanical Drawing All
472.44,433.07 to 653.54,539.37 on Mechanical Drawing All
2204.72,2598.43 to 2066.93,2755.91 on Mechanical Drawing All
834.65,1070.87 to 984.25,1181.1 on Mechanical Drawing All
1700.79,2393.7 to 1822.83,2322.83 on Mechanical Drawing All
2204.72,433.07 to 2055.12,539.37 on Mechanical Drawing All
0,0 to 2482.28,1657.48 on Mechanical Drawing All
